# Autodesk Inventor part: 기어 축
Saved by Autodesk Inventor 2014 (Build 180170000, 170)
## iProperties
Created: 2026-08
Part Number: 기어 축
Material: 강철, 합금
Document SubType Name: Modeling
Designer: dg
Density: 7.85 g/cm^3
Appearance: 반연마
Mass: 99.8337 g
Surface Area: 48.6736 cm^2
Volume: 12.7177 cm^3
Author: jhkim
Creation Date: 2026-07-31
Sending System: Autodesk Inventor 2027
Preprocessor: ST-DEVELOPER v20.1
Author: dg
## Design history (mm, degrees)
node "기어 축1"
node "솔리드1"
node "기준1"
